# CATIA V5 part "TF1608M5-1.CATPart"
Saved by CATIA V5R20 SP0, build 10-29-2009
Part number: TF1608M5-1
Revision: ANY
Definition: UNKNOWN
Nomenclature: TF1608M5-1
Source: Unknown
Bounding box of the stored display mesh (mm): x -3.757 to 3.757, y 0 to 21.45, z -3.95 to 3.95
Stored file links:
  C:\Users\Utente\Desktop\IO LAVORO\3D X SITO CF\CUMSA\3D files RCM\RCM 163808\TF1608M5-1.CATPart
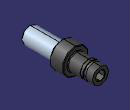
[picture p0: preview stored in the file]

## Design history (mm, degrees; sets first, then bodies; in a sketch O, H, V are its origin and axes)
Body1 "Chaflán2" (main body)
  Solid1: solid without history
